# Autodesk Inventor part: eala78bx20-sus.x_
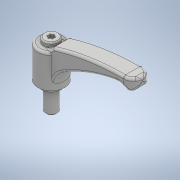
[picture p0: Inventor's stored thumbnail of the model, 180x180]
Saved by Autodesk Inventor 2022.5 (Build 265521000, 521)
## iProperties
Created: 2018-05
Part Number: eala78bx20-sus.x_
Material: 一般
Document SubType Name: Modeling
Designer: imaocorp
Density: 1 g/cm^3
Appearance: 既定
Sending System: SOLIDWORKS 2016-2016286
MC: AMD64
MC_MODEL: AMD64 Family 21 Model 2 Stepping 0, AuthenticAMD
OS: Windows_NT
FRU: Parasolid Version 28.0, build 224,  7-29-2016
FORMAT: text
GUISE: transmit
KEY: eala78bx20-sus
FILE: eala78bx20-sus.x_t
DATE: Fri May 18 11:31:53 2018
Author: imaocorp
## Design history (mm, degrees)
feature "Base1"
node "ソリッド1"
